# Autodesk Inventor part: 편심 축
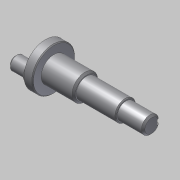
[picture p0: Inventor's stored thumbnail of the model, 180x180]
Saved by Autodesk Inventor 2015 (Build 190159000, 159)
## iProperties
Created: 2015-10
Part Number: 편심 축
Document SubType Name: Modeling
Designer: mdu
Density: 7.86 g/cm^3
Material: 강철, 연강
Mass: 78.4913 g
Surface Area: 37.9919 cm^2
Volume: 9.98617 cm^3
Appearance: 기본값
Author: mdu
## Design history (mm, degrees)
sketch "스케치1"
  geometry: L1 (1.75, -12.001)-(1.75, 11.999) reference; L2 (-16.95, -14)-(-16.95, 14) reference; L3 (-36.25, -18.06)-(-36.25, 18.06) reference; L4 (-41.25, 0)-(20.75, 0); L5 (-41.25, 0)-(-41.25, 12.5); L6 (-41.25, 12.5)-(-36.25, 12.5); L7 (-36.25, 12.5)-(-36.25, 7.5); L8 (-36.25, 7.5)-(-17.25, 7.5); L9 (-17.25, 6)-(5.75, 6); L10 (20.75, 5)-(20.75, 0); L11 (5.75, 6)-(5.75, 5); L12 (5.75, 5)-(20.75, 5); L13 (-17.25, -13.7)-(-17.25, 13.7) reference; L14 (-17.25, 7.5)-(-17.25, 6); 2 further points
  constraints: 20 end point, 7 perpendicular, 5 point on line, 1 collinear, 1 midpoint, 1 parallel
  dimensions: "d0" = 12 diameter of L9 L4; "d1" = 15 diameter of L8 L4; "d2" = 25 diameter of L6 L4; "d3" = 5 distance of L5.end L6.end; "d4" = 62 distance of L4.start L4.end; "d5" = 10 diameter of L12 L4; "d6" = 15 distance of L11.end L10.start
revolve "회전1" sketch "스케치1" stored, may be unused: angle "d7" = 90 deg
sketch "스케치2"
  geometry: C1 r 4 at (0, -7.5); C2 r 5 at (0, -7.5); C3 r 12.5 at (0, 0) reference; 1 further point
  constraints: 2 centre point, 1 coincident, 1 tangent, 1 vertical alignment
  dimensions: "d8" = 8 diameter of C1; "d9" = 7.5 distance of point (0, 0) C1.centre
extrude "돌출1" join sketch "스케치2" distance "d10" = 10; taper "d11" = 0 deg
extrude "돌출2" join sketch "스케치2" distance "d12" = 0.5; taper "d13" = 0 deg
node "작업 평면1"
sketch "스케치3"
  geometry: L1 (-7.5, 5)-(-7.5, -5) reference; L2 (-7.5, 1.5)-(3, 1.5); L3 (3, -1.5)-(-7.5, -1.5); A1 r 1.5 centre (3, 0) between (3, -1.5) and (3, 1.5); 2 further points
  constraints: 4 end point, 2 perpendicular, 2 point on circle, 2 point on line, 2 tangent, 1 centre point, 1 horizontal alignment, 1 midpoint
  dimensions: "d14" = 3 distance between parallel lines of L3 L2; "d15" = 12 dimension on A1 L1
extrude "돌출3" cut sketch "스케치3" distance "d16" = 1.8; taper "d17" = 0 deg
chamfer "모따기1" distance "d18" = 1; stored, may be unused: second distance "d19" = 2, angle "d20" = 45 deg
chamfer "모따기2" distance "d21" = 0.5; stored, may be unused: second distance "d22" = 2, angle "d23" = 45 deg
node "솔리드1"
node "참조1"
node "참조2"
node "참조3"
node "참조4"
